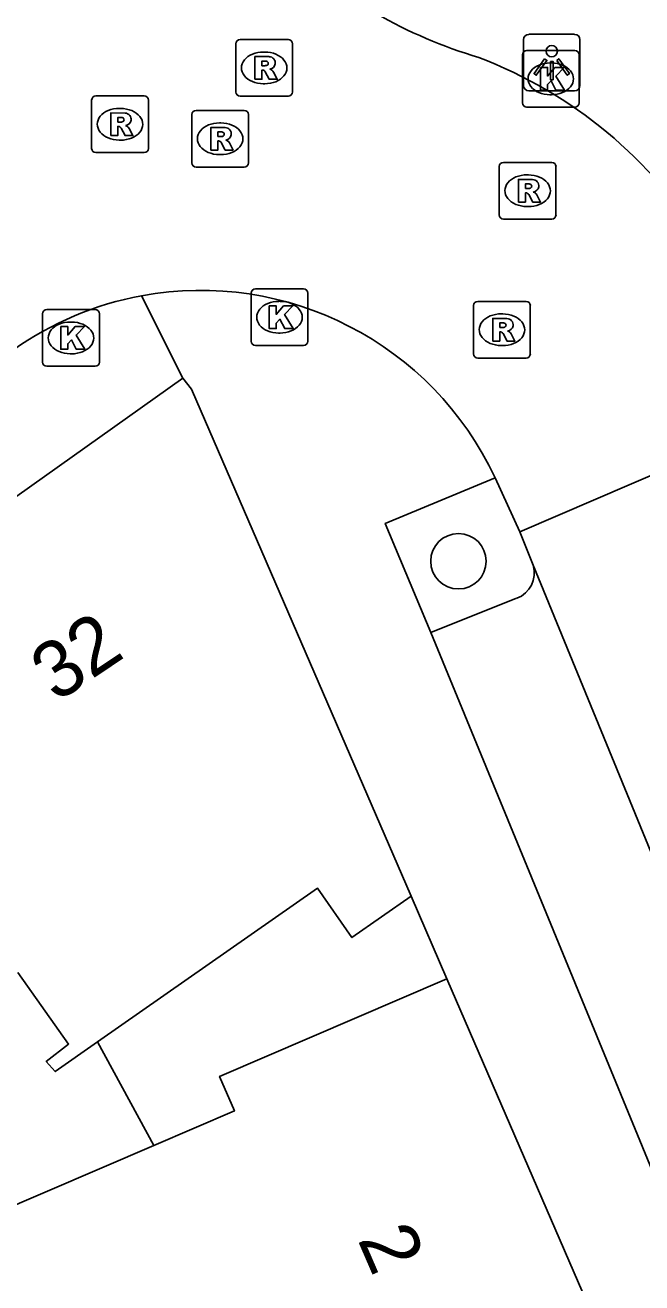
# Model space of a CAD drawing. Extents: x 161771 to 163125, y 382479 to 383177.
# Drawn here: x 161911.34 to 161922.22, y 383056.78 to 383078.97 of the extents above; entities that cross this region are included whole.
import ezdxf

# ---------------------------------------------------------------- set-up
doc = ezdxf.new("R2010")
doc.units = 0
for name, color, linetype in [('IMGEO_Boom', 7, 'Continuous'), ('IMGEO_Kolk', 7, 'Continuous'), ('IMGEO_Lichtpunt', 7, 'Continuous'), ('IMGEO_Pand', 7, 'Continuous'), ('IMGEO_Pand_nummerreeks', 7, 'Continuous'), ('IMGEO_Parkeervlak_open', 7, 'Continuous'), ('IMGEO_Rijbaan_lokaal_open', 7, 'Continuous'), ('IMGEO_Rioolput', 7, 'Continuous'), ('IMGEO_Voetpad_open', 7, 'Continuous')]:
    doc.layers.add(name, color=color, linetype=linetype)

msp = doc.modelspace()

# ---------------------------------------------------------------- linework, layer by layer
at = {"layer": 'IMGEO_Boom'}
msp.add_circle((161918.987, 383069.512), 0.489, dxfattribs=at)
at = {"layer": 'IMGEO_Kolk'}
for p, q in [((161920.115, 383077.596), (161920.115, 383078.448)), ((161920.19, 383078.522), (161921.042, 383078.522)), ((161921.116, 383078.448), (161921.116, 383077.596)), ((161920.603, 383078.302), (161920.628, 383078.302)), ((161920.626, 383077.742), (161920.601, 383077.742)), ((161921.042, 383077.522), (161920.19, 383077.522)), ((161915.328, 383073.391), (161915.328, 383074.243)), ((161915.403, 383074.317), (161916.255, 383074.317)), ((161916.329, 383074.243), (161916.329, 383073.391)), ((161911.724, 383073.951), (161912.576, 383073.951)), ((161915.816, 383074.097), (161915.841, 383074.097)), ((161911.649, 383073.025), (161911.649, 383073.877)), ((161912.137, 383073.731), (161912.162, 383073.731)), ((161912.65, 383073.877), (161912.65, 383073.025)), ((161915.839, 383073.537), (161915.814, 383073.537)), ((161916.255, 383073.317), (161915.403, 383073.317)), ((161912.16, 383073.171), (161912.135, 383073.171)), ((161912.576, 383072.951), (161911.724, 383072.951))]:
    msp.add_line(p, q, dxfattribs=at)
for points in [[(161920.115, 383077.596), (161920.115, 383078.448)], [(161920.19, 383078.522), (161921.042, 383078.522)], [(161921.116, 383078.448), (161921.116, 383077.596)], [(161920.436, 383078.222), (161920.559, 383078.222), (161920.559, 383078.071), (161920.689, 383078.222), (161920.853, 383078.222), (161920.707, 383078.071), (161920.86, 383077.822), (161920.708, 383077.822), (161920.623, 383077.986), (161920.559, 383077.919), (161920.559, 383077.822), (161920.436, 383077.822), (161920.436, 383078.222)], [(161921.042, 383077.522), (161920.19, 383077.522)], [(161915.328, 383073.391), (161915.328, 383074.243)], [(161915.403, 383074.317), (161916.255, 383074.317)], [(161916.329, 383074.243), (161916.329, 383073.391)], [(161911.724, 383073.951), (161912.576, 383073.951)], [(161915.649, 383074.017), (161915.772, 383074.017), (161915.772, 383073.866), (161915.902, 383074.017), (161916.066, 383074.017), (161915.92, 383073.866), (161916.073, 383073.617), (161915.921, 383073.617), (161915.836, 383073.781), (161915.772, 383073.714), (161915.772, 383073.617), (161915.649, 383073.617), (161915.649, 383074.017)], [(161911.649, 383073.025), (161911.649, 383073.877)], [(161912.65, 383073.877), (161912.65, 383073.025)], [(161911.97, 383073.651), (161912.093, 383073.651), (161912.093, 383073.5), (161912.223, 383073.651), (161912.387, 383073.651), (161912.241, 383073.5), (161912.394, 383073.251), (161912.242, 383073.251), (161912.157, 383073.415), (161912.093, 383073.348), (161912.093, 383073.251), (161911.97, 383073.251), (161911.97, 383073.651)], [(161916.255, 383073.317), (161915.403, 383073.317)], [(161912.576, 383072.951), (161911.724, 383072.951)]]:
    msp.add_lwpolyline(points, dxfattribs=at)
for centre, start, end in [((161920.192, 383078.446), 91.552, 178.448), ((161920.192, 383078.446), 91.552, 178.448), ((161921.04, 383078.446), 1.552, 88.448), ((161921.04, 383078.446), 1.552, 88.448), ((161920.192, 383077.598), 181.552, 268.448), ((161920.192, 383077.598), 181.552, 268.448), ((161921.04, 383077.598), 271.552, 358.448), ((161921.04, 383077.598), 271.552, 358.448), ((161915.405, 383074.241), 91.552, 178.448), ((161915.405, 383074.241), 91.552, 178.448), ((161916.253, 383074.241), 1.552, 88.448), ((161916.253, 383074.241), 1.552, 88.448), ((161911.726, 383073.875), 91.552, 178.448), ((161911.726, 383073.875), 91.552, 178.448), ((161912.574, 383073.875), 1.552, 88.448), ((161912.574, 383073.875), 1.552, 88.448), ((161915.405, 383073.393), 181.552, 268.448), ((161915.405, 383073.393), 181.552, 268.448), ((161916.253, 383073.393), 271.552, 358.448), ((161916.253, 383073.393), 271.552, 358.448), ((161911.726, 383073.027), 181.552, 268.448), ((161911.726, 383073.027), 181.552, 268.448), ((161912.574, 383073.027), 271.552, 358.448), ((161912.574, 383073.027), 271.552, 358.448)]:
    msp.add_arc(centre, 0.0765, start, end, dxfattribs=at)
for centre, major_axis, ratio, start_param, end_param in [((161920.602, 383078.022), (-0.387, 0.002), 0.722429, 4.712389, 7.853982), ((161920.627, 383078.022), (-0.39, 0.002), 0.717154, 1.570796, 4.712389), ((161915.815, 383073.817), (-0.387, 0.002), 0.722429, 4.712389, 7.853982), ((161915.84, 383073.817), (-0.39, 0.002), 0.717154, 1.570796, 4.712389), ((161912.136, 383073.451), (-0.387, 0.002), 0.722429, 4.712389, 7.853982), ((161912.161, 383073.451), (-0.39, 0.002), 0.717154, 1.570796, 4.712389)]:
    msp.add_ellipse(centre, major_axis=major_axis, ratio=ratio, start_param=start_param, end_param=end_param, dxfattribs=at)
at = {"layer": 'IMGEO_Lichtpunt'}
for p, q in [((161920.134, 383078.712), (161920.134, 383077.905)), ((161920.134, 383078.712), (161920.134, 383077.905)), ((161921.036, 383078.807), (161920.228, 383078.807)), ((161921.036, 383078.807), (161920.228, 383078.807)), ((161921.13, 383077.905), (161921.13, 383078.712)), ((161921.13, 383077.905), (161921.13, 383078.712)), ((161920.228, 383077.811), (161921.036, 383077.811)), ((161920.228, 383077.811), (161921.036, 383077.811))]:
    msp.add_line(p, q, dxfattribs=at)
for points in [[(161920.508, 383078.376), (161920.547, 383078.348), (161920.359, 383078.086), (161920.321, 383078.113), (161920.508, 383078.376)], [(161920.61, 383078.328), (161920.657, 383078.328), (161920.657, 383078.006), (161920.61, 383078.006), (161920.61, 383078.328)], [(161920.72, 383078.348), (161920.758, 383078.375), (161920.945, 383078.113), (161920.906, 383078.085), (161920.72, 383078.348)]]:
    msp.add_lwpolyline(points, dxfattribs=at)
msp.add_circle((161920.633, 383078.51), 0.0994, dxfattribs=at)
for centre, start, end in [((161920.228, 383078.712), 90, 180), ((161920.228, 383078.712), 90, 180), ((161921.036, 383078.712), 0, 90), ((161921.036, 383078.712), 0, 90), ((161920.228, 383077.905), 180, 270), ((161920.228, 383077.905), 180, 270), ((161921.036, 383077.905), 270, 0), ((161921.036, 383077.905), 270, 360)]:
    msp.add_arc(centre, 0.0946, start, end, dxfattribs=at)
at = {"layer": 'IMGEO_Pand'}
for points in [[(161906.941, 383067.33), (161906.797, 383067.535), (161914.126, 383072.74)], [(161914.126, 383072.74), (161914.277, 383072.549), (161918.153, 383063.602)], [(161912.616, 383061.032), (161916.5, 383063.742), (161917.108, 383062.872), (161918.153, 383063.602)], [(161918.153, 383063.602), (161918.783, 383062.147)], [(161912.616, 383061.032), (161911.871, 383060.509), (161911.712, 383060.688), (161912.106, 383060.994), (161911.21, 383062.256)], [(161918.783, 383062.147), (161914.772, 383060.425), (161915.034, 383059.814), (161913.613, 383059.205)], [(161921.637, 383054.403), (161921.944, 383054.534), (161922.059, 383054.584), (161918.783, 383062.147)], [(161913.613, 383059.205), (161912.616, 383061.032)], [(161913.613, 383059.205), (161906.938, 383056.339)]]:
    msp.add_lwpolyline(points, dxfattribs=at)
at = {"layer": 'IMGEO_Parkeervlak_open'}
msp.add_lwpolyline([(161920.014, 383068.858), (161918.501, 383068.252)], dxfattribs=at)
msp.add_arc((161919.843, 383069.308), 0.482, 290.8495, 15.8629, dxfattribs=at)
at = {"layer": 'IMGEO_Rijbaan_lokaal_open'}
for points in [[(161920.07, 383070.029), (161924.683, 383072.01)], [(161919.632, 383070.986), (161920.07, 383070.029)], [(161920.07, 383070.029), (161920.306, 383069.44)], [(161920.306, 383069.44), (161927.275, 383052.464)]]:
    msp.add_lwpolyline(points, dxfattribs=at)
for centre, radius, start, end in [((161921.791, 383086.618), 8.576, 240.2144, 253.4342), ((161916.527, 383070.965), 7.949, 31.3149, 69.2274), ((161914.44, 383068.563), 5.729, 100.5157, 125.2626), ((161914.438, 383068.558), 5.733, 25.0504, 100.49)]:
    msp.add_arc(centre, radius, start, end, dxfattribs=at)
at = {"layer": 'IMGEO_Rioolput'}
for p, q in [((161915.058, 383077.789), (161915.058, 383078.641)), ((161915.133, 383078.715), (161915.985, 383078.715)), ((161916.059, 383078.641), (161916.059, 383077.789)), ((161915.546, 383078.495), (161915.571, 383078.495)), ((161912.589, 383077.72), (161913.441, 383077.72)), ((161915.569, 383077.935), (161915.544, 383077.935)), ((161912.514, 383076.794), (161912.514, 383077.646)), ((161913.002, 383077.5), (161913.027, 383077.5)), ((161913.515, 383077.646), (161913.515, 383076.794)), ((161915.985, 383077.715), (161915.133, 383077.715)), ((161914.281, 383076.539), (161914.281, 383077.391)), ((161914.356, 383077.465), (161915.208, 383077.465)), ((161915.282, 383077.391), (161915.282, 383076.539)), ((161914.769, 383077.245), (161914.794, 383077.245)), ((161913.025, 383076.94), (161913, 383076.94)), ((161913.441, 383076.72), (161912.589, 383076.72)), ((161914.792, 383076.685), (161914.767, 383076.685)), ((161915.208, 383076.465), (161914.356, 383076.465)), ((161919.707, 383075.622), (161919.707, 383076.474)), ((161919.782, 383076.548), (161920.634, 383076.548)), ((161920.708, 383076.474), (161920.708, 383075.622)), ((161920.195, 383076.328), (161920.22, 383076.328)), ((161920.218, 383075.768), (161920.193, 383075.768)), ((161920.634, 383075.548), (161919.782, 383075.548)), ((161919.254, 383073.17), (161919.254, 383074.022)), ((161919.329, 383074.096), (161920.181, 383074.096)), ((161920.255, 383074.022), (161920.255, 383073.17)), ((161919.742, 383073.876), (161919.767, 383073.876)), ((161919.765, 383073.316), (161919.74, 383073.316)), ((161920.181, 383073.096), (161919.329, 383073.096))]:
    msp.add_line(p, q, dxfattribs=at)
for points in [[(161915.058, 383077.789), (161915.058, 383078.641)], [(161915.133, 383078.715), (161915.985, 383078.715)], [(161916.059, 383078.641), (161916.059, 383077.789)], [(161915.647, 383078.413), (161915.395, 383078.415), (161915.395, 383078.015)], [(161915.395, 383078.015), (161915.519, 383078.015), (161915.519, 383078.177), (161915.53, 383078.177)], [(161915.573, 383078.334), (161915.519, 383078.334), (161915.519, 383078.253)], [(161915.519, 383078.253), (161915.571, 383078.253)], [(161915.577, 383078.148), (161915.648, 383078.015), (161915.788, 383078.015), (161915.723, 383078.141)], [(161912.589, 383077.72), (161913.441, 383077.72)], [(161912.514, 383076.794), (161912.514, 383077.646)], [(161913.515, 383077.646), (161913.515, 383076.794)], [(161915.985, 383077.715), (161915.133, 383077.715)], [(161913.103, 383077.418), (161912.851, 383077.42), (161912.851, 383077.02)], [(161913.029, 383077.339), (161912.975, 383077.339), (161912.975, 383077.258)], [(161914.281, 383076.539), (161914.281, 383077.391)], [(161914.356, 383077.465), (161915.208, 383077.465)], [(161915.282, 383077.391), (161915.282, 383076.539)], [(161912.851, 383077.02), (161912.975, 383077.02), (161912.975, 383077.182), (161912.986, 383077.182)], [(161912.975, 383077.258), (161913.027, 383077.258)], [(161913.033, 383077.153), (161913.104, 383077.02), (161913.244, 383077.02), (161913.179, 383077.146)], [(161914.87, 383077.163), (161914.618, 383077.165), (161914.618, 383076.765)], [(161914.796, 383077.084), (161914.742, 383077.084), (161914.742, 383077.003)], [(161914.618, 383076.765), (161914.742, 383076.765), (161914.742, 383076.927), (161914.753, 383076.927)], [(161914.742, 383077.003), (161914.794, 383077.003)], [(161914.8, 383076.898), (161914.871, 383076.765), (161915.011, 383076.765), (161914.946, 383076.891)], [(161913.441, 383076.72), (161912.589, 383076.72)], [(161915.208, 383076.465), (161914.356, 383076.465)], [(161919.707, 383075.622), (161919.707, 383076.474)], [(161919.782, 383076.548), (161920.634, 383076.548)], [(161920.708, 383076.474), (161920.708, 383075.622)], [(161920.296, 383076.246), (161920.044, 383076.248), (161920.044, 383075.848)], [(161920.222, 383076.167), (161920.168, 383076.167), (161920.168, 383076.086)], [(161920.044, 383075.848), (161920.168, 383075.848), (161920.168, 383076.01), (161920.179, 383076.01)], [(161920.168, 383076.086), (161920.22, 383076.086)], [(161920.226, 383075.981), (161920.297, 383075.848), (161920.437, 383075.848), (161920.372, 383075.974)], [(161920.634, 383075.548), (161919.782, 383075.548)], [(161919.254, 383073.17), (161919.254, 383074.022)], [(161919.329, 383074.096), (161920.181, 383074.096)], [(161920.255, 383074.022), (161920.255, 383073.17)], [(161919.843, 383073.794), (161919.591, 383073.796), (161919.591, 383073.396)], [(161919.591, 383073.396), (161919.715, 383073.396), (161919.715, 383073.558), (161919.726, 383073.558)], [(161919.769, 383073.715), (161919.715, 383073.715), (161919.715, 383073.634)], [(161919.715, 383073.634), (161919.767, 383073.634)], [(161919.773, 383073.529), (161919.844, 383073.396), (161919.984, 383073.396), (161919.919, 383073.522)], [(161920.181, 383073.096), (161919.329, 383073.096)]]:
    msp.add_lwpolyline(points, dxfattribs=at)
for centre, radius, start, end in [((161915.135, 383078.639), 0.0765, 91.552, 178.448), ((161915.135, 383078.639), 0.0765, 91.552, 178.448), ((161915.983, 383078.639), 0.0765, 1.552, 88.448), ((161915.983, 383078.639), 0.0765, 1.552, 88.448), ((161915.646, 383078.303), 0.109, 350.3612, 89.416), ((161915.529, 383078.124), 0.0533, 26.0293, 88.6989), ((161915.555, 383078.442), 0.19, 274.7715, 282.9687), ((161915.579, 383078.238), 0.0964, 77.0061, 93.1865), ((161915.593, 383078.295), 0.0378, 276.6634, 79.6772), ((161915.644, 383078.303), 0.112, 277.5842, 350.9817), ((161915.628, 383078.088), 0.108, 29.5134, 73.7905), ((161912.591, 383077.644), 0.0765, 91.552, 178.448), ((161912.591, 383077.644), 0.0765, 91.552, 178.448), ((161913.439, 383077.644), 0.0765, 1.552, 88.448), ((161913.439, 383077.644), 0.0765, 1.552, 88.448), ((161915.135, 383077.791), 0.0765, 181.552, 268.448), ((161915.135, 383077.791), 0.0765, 181.552, 268.448), ((161915.983, 383077.791), 0.0765, 271.552, 358.448), ((161915.983, 383077.791), 0.0765, 271.552, 358.448), ((161913.035, 383077.243), 0.0964, 77.0061, 93.1865), ((161913.049, 383077.3), 0.0378, 276.6634, 79.6772), ((161913.102, 383077.308), 0.109, 350.3612, 89.416), ((161913.1, 383077.308), 0.112, 277.5842, 350.9817), ((161914.358, 383077.389), 0.0765, 91.552, 178.448), ((161914.358, 383077.389), 0.0765, 91.552, 178.448), ((161915.206, 383077.389), 0.0765, 1.552, 88.448), ((161915.206, 383077.389), 0.0765, 1.552, 88.448), ((161912.985, 383077.129), 0.0533, 26.0293, 88.6989), ((161913.011, 383077.447), 0.19, 274.7715, 282.9687), ((161913.084, 383077.093), 0.108, 29.5134, 73.7905), ((161914.802, 383076.988), 0.0964, 77.0061, 93.1865), ((161914.816, 383077.045), 0.0378, 276.6634, 79.6772), ((161914.869, 383077.053), 0.109, 350.3612, 89.416), ((161914.752, 383076.874), 0.0533, 26.0293, 88.6989), ((161914.778, 383077.192), 0.19, 274.7715, 282.9687), ((161914.867, 383077.053), 0.112, 277.5842, 350.9817), ((161914.851, 383076.838), 0.108, 29.5134, 73.7905), ((161912.591, 383076.796), 0.0765, 181.552, 268.448), ((161912.591, 383076.796), 0.0765, 181.552, 268.448), ((161913.439, 383076.796), 0.0765, 271.552, 358.448), ((161913.439, 383076.796), 0.0765, 271.552, 358.448), ((161914.358, 383076.541), 0.0765, 181.552, 268.448), ((161914.358, 383076.541), 0.0765, 181.552, 268.448), ((161915.206, 383076.541), 0.0765, 271.552, 358.448), ((161915.206, 383076.541), 0.0765, 271.552, 358.448), ((161919.784, 383076.472), 0.0765, 91.552, 178.448), ((161919.784, 383076.472), 0.0765, 91.552, 178.448), ((161920.632, 383076.472), 0.0765, 1.552, 88.448), ((161920.632, 383076.472), 0.0765, 1.552, 88.448), ((161920.228, 383076.071), 0.0964, 77.0061, 93.1865), ((161920.295, 383076.136), 0.109, 350.3612, 89.416), ((161920.178, 383075.957), 0.0533, 26.0293, 88.6989), ((161920.204, 383076.275), 0.19, 274.7715, 282.9687), ((161920.242, 383076.128), 0.0378, 276.6634, 79.6772), ((161920.293, 383076.136), 0.112, 277.5842, 350.9817), ((161920.277, 383075.921), 0.108, 29.5134, 73.7905), ((161919.784, 383075.624), 0.0765, 181.552, 268.448), ((161919.784, 383075.624), 0.0765, 181.552, 268.448), ((161920.632, 383075.624), 0.0765, 271.552, 358.448), ((161920.632, 383075.624), 0.0765, 271.552, 358.448), ((161919.331, 383074.02), 0.0765, 91.552, 178.448), ((161919.331, 383074.02), 0.0765, 91.552, 178.448), ((161920.179, 383074.02), 0.0765, 1.552, 88.448), ((161920.179, 383074.02), 0.0765, 1.552, 88.448), ((161919.842, 383073.684), 0.109, 350.3612, 89.416), ((161919.725, 383073.505), 0.0533, 26.0293, 88.6989), ((161919.751, 383073.823), 0.19, 274.7715, 282.9687), ((161919.775, 383073.619), 0.0964, 77.0061, 93.1865), ((161919.789, 383073.676), 0.0378, 276.6634, 79.6772), ((161919.84, 383073.684), 0.112, 277.5842, 350.9817), ((161919.824, 383073.469), 0.108, 29.5134, 73.7905), ((161919.331, 383073.172), 0.0765, 181.552, 268.448), ((161919.331, 383073.172), 0.0765, 181.552, 268.448), ((161920.179, 383073.172), 0.0765, 271.552, 358.448), ((161920.179, 383073.172), 0.0765, 271.552, 358.448)]:
    msp.add_arc(centre, radius, start, end, dxfattribs=at)
for centre, major_axis, ratio, start_param, end_param in [((161915.545, 383078.215), (-0.387, 0.002), 0.722429, 4.712389, 7.853982), ((161915.57, 383078.215), (-0.39, 0.002), 0.717154, 1.570796, 4.712389), ((161913.001, 383077.22), (-0.387, 0.002), 0.722429, 4.712389, 7.853982), ((161913.026, 383077.22), (-0.39, 0.002), 0.717154, 1.570796, 4.712389), ((161914.768, 383076.965), (-0.387, 0.002), 0.722429, 4.712389, 7.853982), ((161914.793, 383076.965), (-0.39, 0.002), 0.717154, 1.570796, 4.712389), ((161920.194, 383076.048), (-0.387, 0.002), 0.722429, 4.712389, 7.853982), ((161920.219, 383076.048), (-0.39, 0.002), 0.717154, 1.570796, 4.712389), ((161919.741, 383073.596), (-0.387, 0.002), 0.722429, 4.712389, 7.853982), ((161919.766, 383073.596), (-0.39, 0.002), 0.717154, 1.570796, 4.712389)]:
    msp.add_ellipse(centre, major_axis=major_axis, ratio=ratio, start_param=start_param, end_param=end_param, dxfattribs=at)
at = {"layer": 'IMGEO_Voetpad_open'}
for points in [[(161913.394, 383074.196), (161914.126, 383072.74)], [(161918.501, 383068.252), (161917.694, 383070.178), (161919.632, 383070.986)], [(161925.161, 383052.062), (161918.501, 383068.252)]]:
    msp.add_lwpolyline(points, dxfattribs=at)

# ---------------------------------------------------------------- texts
at = {"layer": 'IMGEO_Pand_nummerreeks'}
for s, rotation, p in [('32', 33.7759, (161911.893, 383067.009)), ('2', 293.4223, (161917.201, 383057.549))]:
    msp.add_text(s, height=1, rotation=rotation, dxfattribs=at).set_placement(p)

doc.saveas('drawing.dxf')
